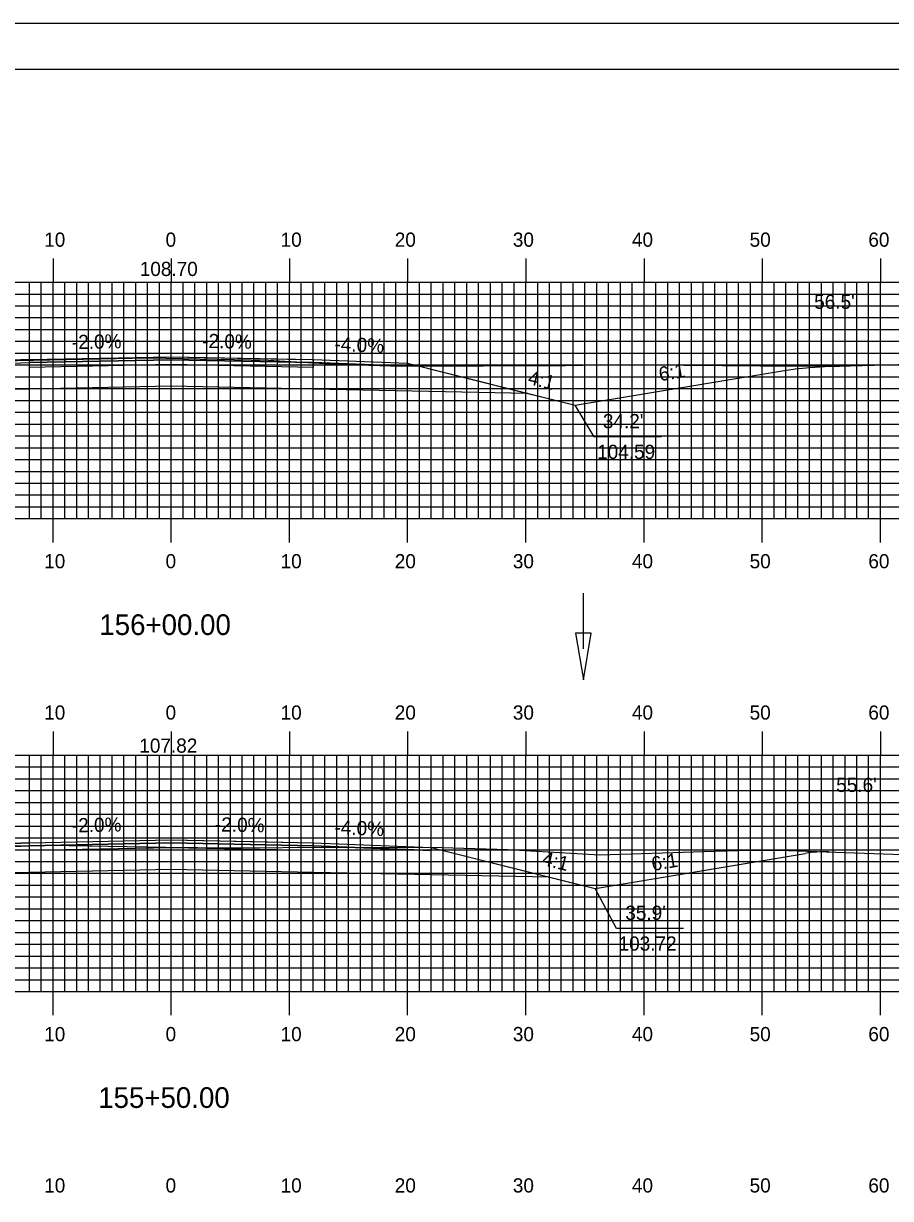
# Model space of a CAD drawing. Extents: x 1779106 to 1779449, y 442591 to 442811.
# Drawn here: x 1779258.8 to 1779332.2, y 442711.2 to 442810.5 of the extents above; entities that cross this region are included whole.
import ezdxf

# ---------------------------------------------------------------- set-up
doc = ezdxf.new("R2010")
doc.units = 0
for name, color, linetype in [('ANNOTATION', 7, 'Continuous'), ('BORDER', 7, 'Continuous'), ('D_Drainage_Ditch_Line', 7, 'Continuous'), ('D_Roadway_Centerline', 7, 'Continuous'), ('D_Roadway_Centerline_Text', 7, 'Continuous'), ('D_Roadway_Edge_Shoulder', 7, 'Continuous'), ('D_Roadway_Edge_TW', 7, 'Continuous'), ('D_Roadway_Pavement', 7, 'Continuous'), ('D_Roadway_SlopeLines', 7, 'Continuous'), ('D_Roadway_SubGrade', 7, 'Continuous'), ('D_Text_Standard', 7, 'Continuous'), ('H_V ANNOTATION', 7, 'Continuous'), ('MAJOR', 7, 'Continuous'), ('MINOR', 7, 'Continuous'), ('PLOT BOUNDARY', 7, 'Continuous'), ('S_Roadway_Centerline', 7, 'Continuous')]:
    doc.layers.add(name, color=color, linetype=linetype)

msp = doc.modelspace()

# ---------------------------------------------------------------- linework, layer by layer
at = {"layer": 'ANNOTATION'}
for points in [[(1779312.802, 442775.589), (1779307.11, 442775.589), (1779305.503, 442778.259)], [(1779314.677, 442734), (1779308.985, 442734), (1779307.184, 442737.384)]]:
    msp.add_lwpolyline(points, dxfattribs=at)
at = {"layer": 'BORDER'}
msp.add_lwpolyline([(1779121.729, 442596.665), (1779441.729, 442596.665), (1779441.729, 442806.665), (1779121.729, 442806.665)], close=True, dxfattribs=at)
at = {"layer": 'D_Drainage_Ditch_Line'}
msp.add_line((1779306.192, 442757.661), (1779306.191, 442762.36), dxfattribs=at)
msp.add_lwpolyline([(1779306.848, 442758.974), (1779305.535, 442758.974), (1779306.192, 442755.037)], close=True, dxfattribs=at)
at = {"layer": 'D_Roadway_Centerline'}
for points in [[(1779251.329, 442781.802), (1779259.33, 442782.122), (1779271.329, 442782.362), (1779281.175, 442782.165), (1779283.329, 442782.122), (1779291.329, 442781.802), (1779301.503, 442779.259), (1779303.138, 442778.851), (1779305.503, 442778.259), (1779322.505, 442781.093), (1779322.855, 442781.151), (1779324.106, 442781.333), (1779325.356, 442781.46), (1779326.606, 442781.534), (1779327.856, 442781.554)], [(1779210.128, 442741.537), (1779211.378, 442741.483), (1779212.589, 442741.387), (1779212.628, 442741.384), (1779212.654, 442741.381), (1779213.879, 442741.241), (1779215.128, 442741.055), (1779237.155, 442737.384), (1779241.156, 442738.384), (1779251.329, 442740.927), (1779259.329, 442741.247), (1779271.328, 442741.487), (1779271.329, 442741.487), (1779278.201, 442741.35), (1779283.329, 442741.247), (1779293.329, 442740.847), (1779303.329, 442738.348), (1779307.184, 442737.384)]]:
    msp.add_lwpolyline(points, dxfattribs=at)
at = {"layer": 'D_Roadway_Edge_Shoulder'}
for points in [[(1779259.33, 442782.122), (1779251.329, 442781.802), (1779251.329, 442781.552), (1779259.33, 442781.872)], [(1779283.329, 442782.122), (1779291.329, 442781.802), (1779291.329, 442781.552), (1779283.329, 442781.872)], [(1779259.329, 442741.247), (1779251.329, 442740.927), (1779251.329, 442740.677), (1779259.329, 442740.997)], [(1779283.329, 442741.247), (1779293.329, 442740.847), (1779293.329, 442740.597), (1779283.329, 442740.997)]]:
    msp.add_lwpolyline(points, close=True, dxfattribs=at)
at = {"layer": 'D_Roadway_Edge_TW'}
for points in [[(1779259.33, 442781.872), (1779259.33, 442782.122), (1779271.329, 442782.362), (1779283.329, 442782.122), (1779283.329, 442781.872), (1779271.329, 442782.112)], [(1779259.329, 442740.997), (1779259.329, 442741.247), (1779271.329, 442741.487), (1779283.329, 442741.247), (1779283.329, 442740.997), (1779271.329, 442741.237)]]:
    msp.add_lwpolyline(points, close=True, dxfattribs=at)
at = {"layer": 'D_Roadway_Pavement'}
for points in [[(1779259.33, 442781.456), (1779259.33, 442781.872), (1779271.329, 442782.112), (1779283.329, 442781.872), (1779283.329, 442781.456), (1779271.329, 442781.696)], [(1779259.329, 442740.581), (1779259.329, 442740.997), (1779271.329, 442741.237), (1779283.329, 442740.997), (1779283.329, 442740.581), (1779271.329, 442740.821)]]:
    msp.add_lwpolyline(points, close=True, dxfattribs=at)
at = {"layer": 'D_Roadway_SlopeLines'}
msp.add_line((1779307.184, 442737.384), (1779324.957, 442740.346), dxfattribs=at)
for points in [[(1779291.329, 442781.802), (1779305.503, 442778.259)], [(1779305.503, 442778.259), (1779322.855, 442781.151), (1779324.106, 442781.333), (1779325.356, 442781.46), (1779326.606, 442781.534), (1779327.856, 442781.554)], [(1779293.329, 442740.847), (1779307.184, 442737.384)]]:
    msp.add_lwpolyline(points, dxfattribs=at)
msp.add_arc((1779326.601, 442730.483), 10, 87.9827, 99.46232, dxfattribs=at)
at = {"layer": 'D_Roadway_SubGrade'}
for points in [[(1779259.33, 442779.622), (1779241.155, 442779.259), (1779251.329, 442781.802), (1779251.329, 442781.552), (1779259.33, 442781.872), (1779271.329, 442782.112), (1779283.329, 442781.872), (1779291.329, 442781.552), (1779291.329, 442781.802), (1779301.503, 442779.259), (1779283.329, 442779.622), (1779271.329, 442779.862)], [(1779259.329, 442738.747), (1779241.156, 442738.384), (1779251.329, 442740.927), (1779251.329, 442740.677), (1779259.329, 442740.997), (1779271.329, 442741.237), (1779283.329, 442740.997), (1779293.329, 442740.597), (1779293.329, 442740.847), (1779303.329, 442738.348), (1779283.329, 442738.747), (1779271.329, 442738.987)]]:
    msp.add_lwpolyline(points, close=True, dxfattribs=at)
at = {"layer": 'MAJOR'}
for p, q in [((1779261.329, 442790.669), (1779261.329, 442788.665)), ((1779271.329, 442790.669), (1779271.329, 442788.665)), ((1779281.329, 442790.669), (1779281.329, 442788.665)), ((1779291.329, 442790.669), (1779291.329, 442788.665)), ((1779301.329, 442790.669), (1779301.329, 442788.665)), ((1779311.329, 442790.669), (1779311.329, 442788.665)), ((1779321.329, 442790.669), (1779321.329, 442788.665)), ((1779331.329, 442790.669), (1779331.329, 442788.665)), ((1779131.329, 442788.665), (1779411.329, 442788.665)), ((1779131.329, 442788.665), (1779411.329, 442788.665)), ((1779261.329, 442768.665), (1779261.329, 442788.665)), ((1779271.329, 442768.665), (1779271.329, 442788.665)), ((1779281.329, 442768.665), (1779281.329, 442788.665)), ((1779291.329, 442768.665), (1779291.329, 442788.665)), ((1779301.329, 442768.665), (1779301.329, 442788.665)), ((1779311.329, 442768.665), (1779311.329, 442788.665)), ((1779321.329, 442768.665), (1779321.329, 442788.665)), ((1779331.329, 442768.665), (1779331.329, 442788.665)), ((1779131.329, 442783.665), (1779411.329, 442783.665)), ((1779131.329, 442778.665), (1779411.329, 442778.665)), ((1779131.329, 442773.665), (1779411.329, 442773.665)), ((1779131.329, 442768.665), (1779411.329, 442768.665)), ((1779131.329, 442768.665), (1779411.329, 442768.665)), ((1779261.329, 442766.661), (1779261.329, 442768.665)), ((1779271.329, 442766.661), (1779271.329, 442768.665)), ((1779281.329, 442766.661), (1779281.329, 442768.665)), ((1779291.329, 442766.661), (1779291.329, 442768.665)), ((1779301.329, 442766.661), (1779301.329, 442768.665)), ((1779311.329, 442766.661), (1779311.329, 442768.665)), ((1779321.329, 442766.661), (1779321.329, 442768.665)), ((1779331.329, 442766.661), (1779331.329, 442768.665)), ((1779261.329, 442750.669), (1779261.329, 442748.665)), ((1779271.329, 442750.669), (1779271.329, 442748.665)), ((1779281.329, 442750.669), (1779281.329, 442748.665)), ((1779291.329, 442750.669), (1779291.329, 442748.665)), ((1779301.329, 442750.669), (1779301.329, 442748.665)), ((1779311.329, 442750.669), (1779311.329, 442748.665)), ((1779321.329, 442750.669), (1779321.329, 442748.665)), ((1779331.329, 442750.669), (1779331.329, 442748.665)), ((1779131.329, 442748.665), (1779411.329, 442748.665)), ((1779131.329, 442748.665), (1779411.329, 442748.665)), ((1779261.329, 442728.665), (1779261.329, 442748.665)), ((1779271.329, 442728.665), (1779271.329, 442748.665)), ((1779281.329, 442728.665), (1779281.329, 442748.665)), ((1779291.329, 442728.665), (1779291.329, 442748.665)), ((1779301.329, 442728.665), (1779301.329, 442748.665)), ((1779311.329, 442728.665), (1779311.329, 442748.665)), ((1779321.329, 442728.665), (1779321.329, 442748.665)), ((1779331.329, 442728.665), (1779331.329, 442748.665)), ((1779131.329, 442743.665), (1779411.329, 442743.665)), ((1779131.329, 442738.665), (1779411.329, 442738.665)), ((1779131.329, 442733.665), (1779411.329, 442733.665)), ((1779131.329, 442728.665), (1779411.329, 442728.665)), ((1779131.329, 442728.665), (1779411.329, 442728.665)), ((1779261.329, 442726.661), (1779261.329, 442728.665)), ((1779271.329, 442726.661), (1779271.329, 442728.665)), ((1779281.329, 442726.661), (1779281.329, 442728.665)), ((1779291.329, 442726.661), (1779291.329, 442728.665)), ((1779301.329, 442726.661), (1779301.329, 442728.665)), ((1779311.329, 442726.661), (1779311.329, 442728.665)), ((1779321.329, 442726.661), (1779321.329, 442728.665)), ((1779331.329, 442726.661), (1779331.329, 442728.665))]:
    msp.add_line(p, q, dxfattribs=at)
at = {"layer": 'MINOR'}
for p, q in [((1779259.329, 442768.665), (1779259.329, 442788.665)), ((1779260.329, 442768.665), (1779260.329, 442788.665)), ((1779262.329, 442768.665), (1779262.329, 442788.665)), ((1779263.329, 442768.665), (1779263.329, 442788.665)), ((1779264.329, 442768.665), (1779264.329, 442788.665)), ((1779265.329, 442768.665), (1779265.329, 442788.665)), ((1779266.329, 442768.665), (1779266.329, 442788.665)), ((1779267.329, 442768.665), (1779267.329, 442788.665)), ((1779268.329, 442768.665), (1779268.329, 442788.665)), ((1779269.329, 442768.665), (1779269.329, 442788.665)), ((1779270.329, 442768.665), (1779270.329, 442788.665)), ((1779272.329, 442768.665), (1779272.329, 442788.665)), ((1779273.329, 442768.665), (1779273.329, 442788.665)), ((1779274.329, 442768.665), (1779274.329, 442788.665)), ((1779275.329, 442768.665), (1779275.329, 442788.665)), ((1779276.329, 442768.665), (1779276.329, 442788.665)), ((1779277.329, 442768.665), (1779277.329, 442788.665)), ((1779278.329, 442768.665), (1779278.329, 442788.665)), ((1779279.329, 442768.665), (1779279.329, 442788.665)), ((1779280.329, 442768.665), (1779280.329, 442788.665)), ((1779282.329, 442768.665), (1779282.329, 442788.665)), ((1779283.329, 442768.665), (1779283.329, 442788.665)), ((1779284.329, 442768.665), (1779284.329, 442788.665)), ((1779285.329, 442768.665), (1779285.329, 442788.665)), ((1779286.329, 442768.665), (1779286.329, 442788.665)), ((1779287.329, 442768.665), (1779287.329, 442788.665)), ((1779288.329, 442768.665), (1779288.329, 442788.665)), ((1779289.329, 442768.665), (1779289.329, 442788.665)), ((1779290.329, 442768.665), (1779290.329, 442788.665)), ((1779292.329, 442768.665), (1779292.329, 442788.665)), ((1779293.329, 442768.665), (1779293.329, 442788.665)), ((1779294.329, 442768.665), (1779294.329, 442788.665)), ((1779295.329, 442768.665), (1779295.329, 442788.665)), ((1779296.329, 442768.665), (1779296.329, 442788.665)), ((1779297.329, 442768.665), (1779297.329, 442788.665)), ((1779298.329, 442768.665), (1779298.329, 442788.665)), ((1779299.329, 442768.665), (1779299.329, 442788.665)), ((1779300.329, 442768.665), (1779300.329, 442788.665)), ((1779302.329, 442768.665), (1779302.329, 442788.665)), ((1779303.329, 442768.665), (1779303.329, 442788.665)), ((1779304.329, 442768.665), (1779304.329, 442788.665)), ((1779305.329, 442768.665), (1779305.329, 442788.665)), ((1779306.329, 442768.665), (1779306.329, 442788.665)), ((1779307.329, 442768.665), (1779307.329, 442788.665)), ((1779308.329, 442768.665), (1779308.329, 442788.665)), ((1779309.329, 442768.665), (1779309.329, 442788.665)), ((1779310.329, 442768.665), (1779310.329, 442788.665)), ((1779312.329, 442768.665), (1779312.329, 442788.665)), ((1779313.329, 442768.665), (1779313.329, 442788.665)), ((1779314.329, 442768.665), (1779314.329, 442788.665)), ((1779315.329, 442768.665), (1779315.329, 442788.665)), ((1779316.329, 442768.665), (1779316.329, 442788.665)), ((1779317.329, 442768.665), (1779317.329, 442788.665)), ((1779318.329, 442768.665), (1779318.329, 442788.665)), ((1779319.329, 442768.665), (1779319.329, 442788.665)), ((1779320.329, 442768.665), (1779320.329, 442788.665)), ((1779322.329, 442768.665), (1779322.329, 442788.665)), ((1779323.329, 442768.665), (1779323.329, 442788.665)), ((1779324.329, 442768.665), (1779324.329, 442788.665)), ((1779325.329, 442768.665), (1779325.329, 442788.665)), ((1779326.329, 442768.665), (1779326.329, 442788.665)), ((1779327.329, 442768.665), (1779327.329, 442788.665)), ((1779328.329, 442768.665), (1779328.329, 442788.665)), ((1779329.329, 442768.665), (1779329.329, 442788.665)), ((1779330.329, 442768.665), (1779330.329, 442788.665)), ((1779131.329, 442787.665), (1779411.329, 442787.665)), ((1779131.329, 442786.665), (1779411.329, 442786.665)), ((1779131.329, 442785.665), (1779411.329, 442785.665)), ((1779131.329, 442784.665), (1779411.329, 442784.665)), ((1779131.329, 442782.665), (1779411.329, 442782.665)), ((1779131.329, 442781.665), (1779411.329, 442781.665)), ((1779131.329, 442780.665), (1779411.329, 442780.665)), ((1779131.329, 442779.665), (1779411.329, 442779.665)), ((1779131.329, 442777.665), (1779411.329, 442777.665)), ((1779131.329, 442776.665), (1779411.329, 442776.665)), ((1779131.329, 442775.665), (1779411.329, 442775.665)), ((1779131.329, 442774.665), (1779411.329, 442774.665)), ((1779131.329, 442772.665), (1779411.329, 442772.665)), ((1779131.329, 442771.665), (1779411.329, 442771.665)), ((1779131.329, 442770.665), (1779411.329, 442770.665)), ((1779131.329, 442769.665), (1779411.329, 442769.665)), ((1779259.329, 442728.665), (1779259.329, 442748.665)), ((1779260.329, 442728.665), (1779260.329, 442748.665)), ((1779262.329, 442728.665), (1779262.329, 442748.665)), ((1779263.329, 442728.665), (1779263.329, 442748.665)), ((1779264.329, 442728.665), (1779264.329, 442748.665)), ((1779265.329, 442728.665), (1779265.329, 442748.665)), ((1779266.329, 442728.665), (1779266.329, 442748.665)), ((1779267.329, 442728.665), (1779267.329, 442748.665)), ((1779268.329, 442728.665), (1779268.329, 442748.665)), ((1779269.329, 442728.665), (1779269.329, 442748.665)), ((1779270.329, 442728.665), (1779270.329, 442748.665)), ((1779272.329, 442728.665), (1779272.329, 442748.665)), ((1779273.329, 442728.665), (1779273.329, 442748.665)), ((1779274.329, 442728.665), (1779274.329, 442748.665)), ((1779275.329, 442728.665), (1779275.329, 442748.665)), ((1779276.329, 442728.665), (1779276.329, 442748.665)), ((1779277.329, 442728.665), (1779277.329, 442748.665)), ((1779278.329, 442728.665), (1779278.329, 442748.665)), ((1779279.329, 442728.665), (1779279.329, 442748.665)), ((1779280.329, 442728.665), (1779280.329, 442748.665)), ((1779282.329, 442728.665), (1779282.329, 442748.665)), ((1779283.329, 442728.665), (1779283.329, 442748.665)), ((1779284.329, 442728.665), (1779284.329, 442748.665)), ((1779285.329, 442728.665), (1779285.329, 442748.665)), ((1779286.329, 442728.665), (1779286.329, 442748.665)), ((1779287.329, 442728.665), (1779287.329, 442748.665)), ((1779288.329, 442728.665), (1779288.329, 442748.665)), ((1779289.329, 442728.665), (1779289.329, 442748.665)), ((1779290.329, 442728.665), (1779290.329, 442748.665)), ((1779292.329, 442728.665), (1779292.329, 442748.665)), ((1779293.329, 442728.665), (1779293.329, 442748.665)), ((1779294.329, 442728.665), (1779294.329, 442748.665)), ((1779295.329, 442728.665), (1779295.329, 442748.665)), ((1779296.329, 442728.665), (1779296.329, 442748.665)), ((1779297.329, 442728.665), (1779297.329, 442748.665)), ((1779298.329, 442728.665), (1779298.329, 442748.665)), ((1779299.329, 442728.665), (1779299.329, 442748.665)), ((1779300.329, 442728.665), (1779300.329, 442748.665)), ((1779302.329, 442728.665), (1779302.329, 442748.665)), ((1779303.329, 442728.665), (1779303.329, 442748.665)), ((1779304.329, 442728.665), (1779304.329, 442748.665)), ((1779305.329, 442728.665), (1779305.329, 442748.665)), ((1779306.329, 442728.665), (1779306.329, 442748.665)), ((1779307.329, 442728.665), (1779307.329, 442748.665)), ((1779308.329, 442728.665), (1779308.329, 442748.665)), ((1779309.329, 442728.665), (1779309.329, 442748.665)), ((1779310.329, 442728.665), (1779310.329, 442748.665)), ((1779312.329, 442728.665), (1779312.329, 442748.665)), ((1779313.329, 442728.665), (1779313.329, 442748.665)), ((1779314.329, 442728.665), (1779314.329, 442748.665)), ((1779315.329, 442728.665), (1779315.329, 442748.665)), ((1779316.329, 442728.665), (1779316.329, 442748.665)), ((1779317.329, 442728.665), (1779317.329, 442748.665)), ((1779318.329, 442728.665), (1779318.329, 442748.665)), ((1779319.329, 442728.665), (1779319.329, 442748.665)), ((1779320.329, 442728.665), (1779320.329, 442748.665)), ((1779322.329, 442728.665), (1779322.329, 442748.665)), ((1779323.329, 442728.665), (1779323.329, 442748.665)), ((1779324.329, 442728.665), (1779324.329, 442748.665)), ((1779325.329, 442728.665), (1779325.329, 442748.665)), ((1779326.329, 442728.665), (1779326.329, 442748.665)), ((1779327.329, 442728.665), (1779327.329, 442748.665)), ((1779328.329, 442728.665), (1779328.329, 442748.665)), ((1779329.329, 442728.665), (1779329.329, 442748.665)), ((1779330.329, 442728.665), (1779330.329, 442748.665)), ((1779131.329, 442747.665), (1779411.329, 442747.665)), ((1779131.329, 442746.665), (1779411.329, 442746.665)), ((1779131.329, 442745.665), (1779411.329, 442745.665)), ((1779131.329, 442744.665), (1779411.329, 442744.665)), ((1779131.329, 442742.665), (1779411.329, 442742.665)), ((1779131.329, 442741.665), (1779411.329, 442741.665)), ((1779131.329, 442740.665), (1779411.329, 442740.665)), ((1779131.329, 442739.665), (1779411.329, 442739.665)), ((1779131.329, 442737.665), (1779411.329, 442737.665)), ((1779131.329, 442736.665), (1779411.329, 442736.665)), ((1779131.329, 442735.665), (1779411.329, 442735.665)), ((1779131.329, 442734.665), (1779411.329, 442734.665)), ((1779131.329, 442732.665), (1779411.329, 442732.665)), ((1779131.329, 442731.665), (1779411.329, 442731.665)), ((1779131.329, 442730.665), (1779411.329, 442730.665)), ((1779131.329, 442729.665), (1779411.329, 442729.665))]:
    msp.add_line(p, q, dxfattribs=at)
at = {"layer": 'PLOT BOUNDARY'}
msp.add_lwpolyline([(1779105.542, 442590.547), (1779445.542, 442590.547), (1779445.542, 442810.547), (1779105.542, 442810.547)], close=True, dxfattribs=at)
at = {"layer": 'S_Roadway_Centerline'}
for points in [[(1779204.323, 442782.626), (1779208.379, 442782.565), (1779224.594, 442782.397), (1779232.647, 442782.554), (1779247.552, 442782.307), (1779256.889, 442782.027), (1779269.461, 442782.27), (1779279.535, 442782.073), (1779285.297, 442781.72), (1779290.781, 442781.564), (1779304.666, 442781.605), (1779309.156, 442781.709), (1779314.679, 442781.638), (1779321.178, 442781.598), (1779327.747, 442781.551), (1779336.863, 442781.816)], [(1779203.403, 442741.748), (1779205.429, 442741.661), (1779215.254, 442741.403), (1779227.205, 442741.499), (1779227.424, 442741.508), (1779227.624, 442741.505), (1779248.292, 442740.919), (1779251.636, 442740.867), (1779261.056, 442741.059), (1779270.858, 442740.865), (1779273.556, 442740.862), (1779276.254, 442740.833), (1779285.251, 442740.863), (1779294.223, 442740.845), (1779299.806, 442740.668), (1779307.59, 442740.221), (1779317.29, 442740.535), (1779320.153, 442740.619), (1779322.749, 442740.624), (1779342.777, 442739.919)]]:
    msp.add_lwpolyline(points, dxfattribs=at)

# ---------------------------------------------------------------- texts
at = {"layer": 'ANNOTATION'}
for s, rotation, p in [('-2.0%', 1.14582, (1779262.936, 442782.995)), ('-2.0%', 358.85424, (1779273.938, 442783.11)), ('-4.0%', 357.70947, (1779285.121, 442782.852)), ('6:1', 9.46221, (1779312.68, 442780.283)), ('4:1', 345.96539, (1779301.429, 442780.075)), ('-2.0%', 1.14571, (1779262.934, 442742.12)), ('-2.0%', 358.85424, (1779275.015, 442742.214)), ('-4.0%', 357.70947, (1779285.121, 442741.977)), ('4:1', 345.96582, (1779302.626, 442739.385)), ('6:1', 9.46389, (1779312.058, 442738.859))]:
    msp.add_text(s, height=1.2, rotation=rotation, dxfattribs=at).set_placement(p)
for s, p in [("34.2'", (1779307.845, 442776.315)), ('104.59', (1779307.357, 442773.715)), ("35.9'", (1779309.741, 442734.726)), ('103.72', (1779309.174, 442732.126))]:
    msp.add_text(s, height=1.2, dxfattribs=at).set_placement(p)
at = {"layer": 'D_Roadway_Centerline'}
for s, p in [('C', (1779271.324, 442782.362)), ('L', (1779271.329, 442782.355)), ('C', (1779271.324, 442741.487)), ('L', (1779271.329, 442741.48))]:
    msp.add_text(s, height=0.0146, dxfattribs=at).set_placement(p)
at = {"layer": 'D_Roadway_Centerline_Text'}
for s, p in [('108.70', (1779268.664, 442789.187)), ('107.82', (1779268.627, 442748.867))]:
    msp.add_text(s, height=1.2, dxfattribs=at).set_placement(p)
at = {"layer": 'D_Text_Standard'}
for s, p in [("56.5'", (1779325.719, 442786.414)), ("55.6'", (1779327.582, 442745.544))]:
    msp.add_text(s, height=1.2, dxfattribs=at).set_placement(p)
at = {"layer": 'H_V ANNOTATION'}
for s, height, p in [('10', 1.2, (1779260.58, 442791.665)), ('0', 1.2, (1779270.847, 442791.665)), ('10', 1.2, (1779280.58, 442791.665)), ('20', 1.2, (1779290.237, 442791.665)), ('30', 1.2, (1779300.227, 442791.665)), ('40', 1.2, (1779310.301, 442791.665)), ('50', 1.2, (1779320.258, 442791.665)), ('60', 1.2, (1779330.301, 442791.665)), ('10', 1.2, (1779260.58, 442764.465)), ('0', 1.2, (1779270.847, 442764.465)), ('10', 1.2, (1779280.58, 442764.465)), ('20', 1.2, (1779290.237, 442764.465)), ('30', 1.2, (1779300.227, 442764.465)), ('40', 1.2, (1779310.301, 442764.465)), ('50', 1.2, (1779320.258, 442764.465)), ('60', 1.2, (1779330.301, 442764.465)), ('156+00.00', 1.75, (1779265.243, 442758.821)), ('10', 1.2, (1779260.58, 442751.665)), ('0', 1.2, (1779270.847, 442751.665)), ('10', 1.2, (1779280.58, 442751.665)), ('20', 1.2, (1779290.237, 442751.665)), ('30', 1.2, (1779300.227, 442751.665)), ('40', 1.2, (1779310.301, 442751.665)), ('50', 1.2, (1779320.258, 442751.665)), ('60', 1.2, (1779330.301, 442751.665)), ('10', 1.2, (1779260.58, 442724.465)), ('0', 1.2, (1779270.847, 442724.465)), ('10', 1.2, (1779280.58, 442724.465)), ('20', 1.2, (1779290.237, 442724.465)), ('30', 1.2, (1779300.227, 442724.465)), ('40', 1.2, (1779310.301, 442724.465)), ('50', 1.2, (1779320.258, 442724.465)), ('60', 1.2, (1779330.301, 442724.465)), ('155+50.00', 1.75, (1779265.149, 442718.821)), ('10', 1.2, (1779260.58, 442711.665)), ('0', 1.2, (1779270.847, 442711.665)), ('10', 1.2, (1779280.58, 442711.665)), ('20', 1.2, (1779290.237, 442711.665)), ('30', 1.2, (1779300.227, 442711.665)), ('40', 1.2, (1779310.301, 442711.665)), ('50', 1.2, (1779320.258, 442711.665)), ('60', 1.2, (1779330.301, 442711.665))]:
    msp.add_text(s, height=height, dxfattribs=at).set_placement(p)

doc.saveas('drawing.dxf')
